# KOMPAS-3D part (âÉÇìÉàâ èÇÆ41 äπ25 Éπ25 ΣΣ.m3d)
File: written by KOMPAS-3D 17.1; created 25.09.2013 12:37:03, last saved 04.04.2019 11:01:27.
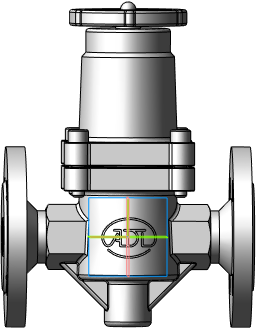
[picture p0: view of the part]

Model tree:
1. Операция без истории:4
